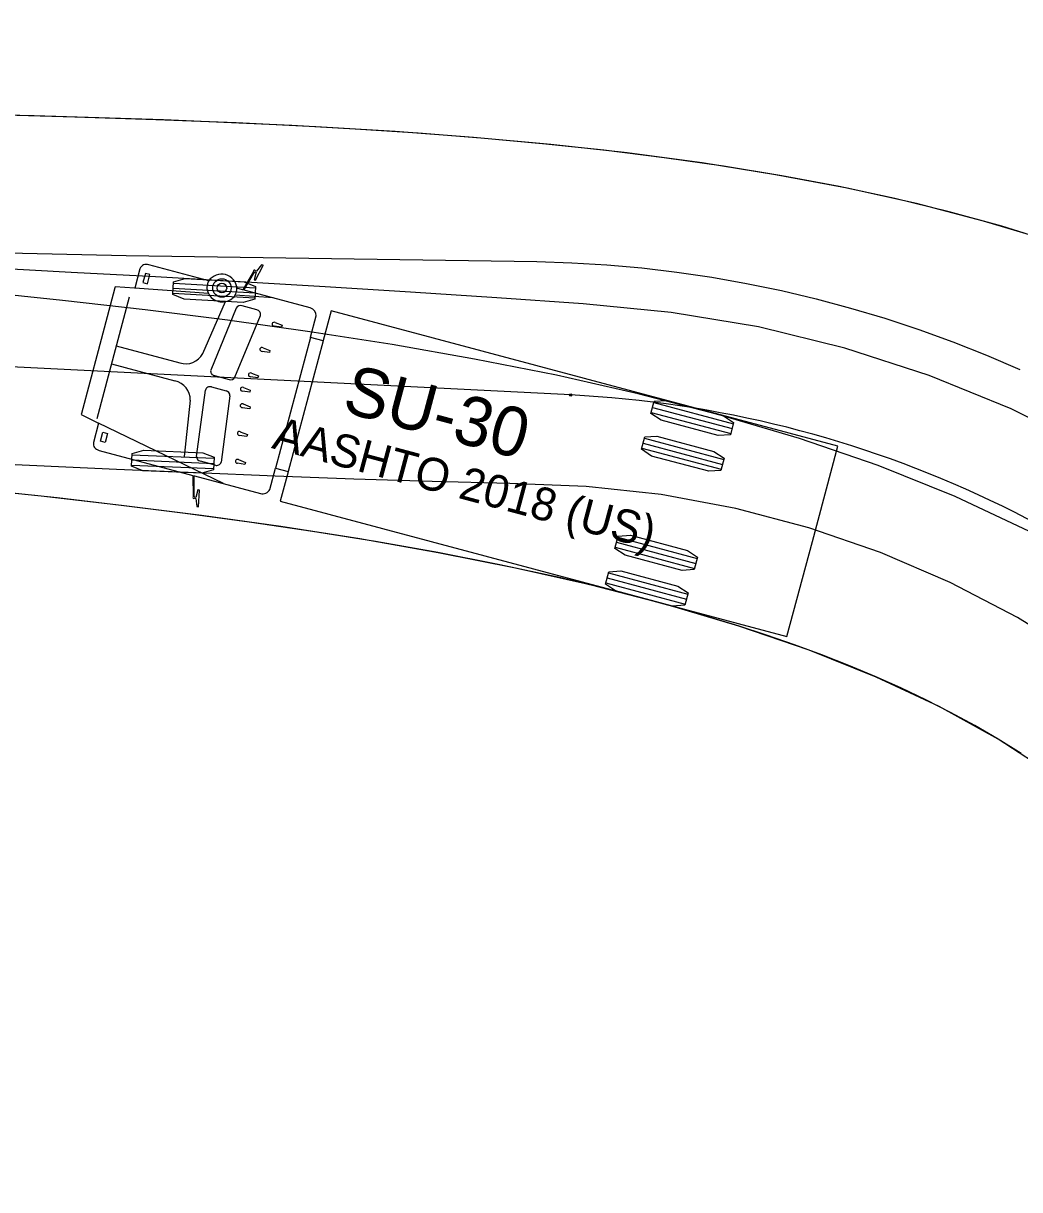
# Model space of a CAD drawing. Extents: x 260275 to 261282, y 610916 to 614143.
# Drawn here: x 261003.29 to 261043.72, y 612552.98 to 612600.34 of the extents above; entities that cross this region are included whole.
import ezdxf

# ---------------------------------------------------------------- set-up
doc = ezdxf.new("R2010")
doc.units = 0
doc.layers.add('TopoDOT_Transients', color=7, linetype='Continuous')

msp = doc.modelspace()

# ---------------------------------------------------------------- linework, layer by layer
at = {"layer": 'TopoDOT_Transients'}
for p, q in [((261025.504, 612585.252), (260776.884, 612597.696)), ((261010.818, 612589.889), (261008.381, 612590.54)), ((261008.244, 612590.188), (261008.146, 612589.822)), ((261008.432, 612590.138), (261008.244, 612590.188)), ((261008.334, 612589.772), (261008.432, 612590.138)), ((261010.801, 612589.377), (261007.813, 612589.59)), ((261008.146, 612589.822), (261008.334, 612589.772)), ((261009.371, 612589.588), (261012.699, 612589.399)), ((261009.383, 612589.796), (261012.711, 612589.607)), ((261007.587, 612589.22), (261006.269, 612584.288)), ((261009.359, 612589.38), (261012.687, 612589.191)), ((261013.429, 612589.191), (261011.884, 612589.301)), ((261010.573, 612586.933), (261011.496, 612589.042)), ((261011.933, 612588.777), (261010.898, 612586.264)), ((261012.763, 612588.712), (261012.168, 612588.871)), ((261011.876, 612585.972), (261012.912, 612588.484)), ((261013.51, 612588.196), (261013.791, 612588.084)), ((261013.769, 612588.004), (261013.471, 612588.047)), ((261013.791, 612588.084), (261013.769, 612588.004)), ((261007.061, 612587.252), (261009.639, 612586.563)), ((261013.019, 612587.171), (261013.299, 612587.059)), ((261014.943, 612587.592), (261013.525, 612582.286)), ((261015.456, 612587.454), (261014.038, 612582.149)), ((261013.278, 612586.979), (261012.979, 612587.022)), ((261013.299, 612587.059), (261013.278, 612586.979)), ((261006.864, 612586.512), (261009.441, 612585.823)), ((261011.046, 612586.037), (261011.642, 612585.878)), ((261012.813, 612585.947), (261012.514, 612585.989)), ((261012.554, 612586.139), (261012.834, 612586.026)), ((261012.834, 612586.026), (261012.813, 612585.947)), ((261010.325, 612582.76), (261010.681, 612585.454)), ((261010.923, 612585.577), (261011.519, 612585.418)), ((261012.483, 612585.364), (261012.184, 612585.407)), ((261012.224, 612585.556), (261012.504, 612585.444)), ((261012.504, 612585.444), (261012.483, 612585.364)), ((261010.066, 612585.037), (261009.815, 612582.76)), ((261011.675, 612585.22), (261011.319, 612582.526)), ((261012.219, 612584.886), (261012.5, 612584.774)), ((261028.884, 612584.948), (261032.105, 612584.087)), ((261012.478, 612584.694), (261012.179, 612584.737)), ((261012.5, 612584.774), (261012.478, 612584.694)), ((261028.777, 612584.545), (261031.997, 612583.684)), ((261028.831, 612584.746), (261032.051, 612583.886)), ((261011.415, 612581.655), (261006.349, 612584.111)), ((261006.424, 612583.378), (261006.522, 612583.744)), ((261006.611, 612583.328), (261006.424, 612583.378)), ((261006.522, 612583.744), (261006.709, 612583.694)), ((261006.709, 612583.694), (261006.611, 612583.328)), ((261012.366, 612583.568), (261012.054, 612583.613)), ((261012.094, 612583.762), (261012.387, 612583.647)), ((261012.387, 612583.647), (261012.366, 612583.568)), ((261028.497, 612583.498), (261031.717, 612582.638)), ((261028.389, 612583.096), (261031.61, 612582.235)), ((261028.443, 612583.297), (261031.664, 612582.436)), ((261007.693, 612582.614), (261011.023, 612582.472)), ((261007.702, 612582.822), (261011.032, 612582.68)), ((261011.077, 612582.402), (261010.481, 612582.562)), ((261012.281, 612582.434), (261011.982, 612582.477)), ((261012.022, 612582.626), (261012.302, 612582.514)), ((261012.302, 612582.514), (261012.281, 612582.434)), ((261007.684, 612582.406), (261011.014, 612582.263)), ((261027.367, 612579.272), (261030.588, 612578.411)), ((261027.421, 612579.473), (261030.641, 612578.612)), ((261027.314, 612579.071), (261030.534, 612578.21)), ((261026.98, 612577.823), (261030.2, 612576.962)), ((261027.034, 612578.024), (261030.254, 612577.163)), ((261026.926, 612577.621), (261030.147, 612576.761))]:
    msp.add_line(p, q, dxfattribs=at)
for points in [[(261045.064, 612591.464), (261043, 612592.102), (261040.864, 612592.69), (261038.66, 612593.227), (261036.396, 612593.714), (261034.077, 612594.152), (261031.71, 612594.542), (261029.299, 612594.888), (261026.85, 612595.192), (261024.367, 612595.457), (261021.855, 612595.686), (261019.319, 612595.883), (261016.76, 612596.051), (261014.183, 612596.194), (261008.981, 612596.419), (261003.728, 612596.585), (260998.439, 612596.713)], [(261044.857, 612591.532), (261042.252, 612592.316), (261039.535, 612593.021), (261036.72, 612593.648), (261033.818, 612594.197), (261030.84, 612594.673), (261027.798, 612595.08), (261024.702, 612595.424), (261021.559, 612595.711), (261018.378, 612595.948), (261015.165, 612596.142), (261011.927, 612596.301), (261008.666, 612596.43), (261005.384, 612596.537), (261002.085, 612596.628)], [(261002.039, 612591.033), (261007.472, 612590.914), (261024.126, 612590.67), (261025.547, 612590.623), (261026.969, 612590.536), (261028.39, 612590.409), (261029.81, 612590.241), (261031.228, 612590.031), (261032.643, 612589.781), (261034.054, 612589.49), (261035.461, 612589.156), (261036.861, 612588.782), (261038.255, 612588.366), (261039.639, 612587.908), (261041.012, 612587.408), (261042.375, 612586.868), (261043.725, 612586.285)], [(261012.691, 612590.251), (261012.734, 612590.24), (261012.735, 612590.239), (261012.661, 612589.93), (261012.66, 612589.928), (261012.714, 612589.914), (261012.716, 612589.916), (261013.02, 612590.514), (261013.021, 612590.517), (261012.958, 612590.533), (261012.755, 612590.282), (261012.754, 612590.282), (261012.708, 612590.294)], [(261046.595, 612583.097), (261043.377, 612584.693), (261040.048, 612586.05), (261036.627, 612587.159), (261033.132, 612588.013), (261029.582, 612588.608), (261026.016, 612588.949), (261022.502, 612589.202), (261019.01, 612589.433), (261015.54, 612589.648), (261012.09, 612589.851), (261008.657, 612590.044), (261005.24, 612590.231), (261001.835, 612590.413)], [(261008.023, 612590.373), (261007.814, 612589.593), (261007.808, 612589.59), (261007.025, 612589.646), (261007.012, 612589.605), (261006.329, 612587.051), (261005.647, 612584.497), (261005.638, 612584.456), (261006.345, 612584.113), (261006.348, 612584.108), (261006.139, 612583.328)], [(261012.627, 612590.274), (261012.627, 612590.273), (261012.194, 612589.528), (261012.181, 612589.524), (261011.96, 612589.583)], [(261014.936, 612588.788), (261012.256, 612589.504), (261012.246, 612589.512), (261012.669, 612590.245), (261012.669, 612590.245)], [(261044.12, 612579.713), (261041.106, 612581.131), (261037.984, 612582.383), (261034.784, 612583.484), (261031.532, 612584.452), (261028.243, 612585.302), (261024.93, 612586.051), (261021.602, 612586.712), (261018.264, 612587.298), (261014.922, 612587.821), (261011.576, 612588.289), (261008.23, 612588.711), (261004.883, 612589.094), (261001.538, 612589.444)], [(261013.292, 612581.417), (261013.524, 612582.283), (261013.528, 612582.285), (261014.037, 612582.149), (261014.035, 612582.138), (261013.714, 612580.937), (261034.279, 612575.44), (261035.312, 612579.305), (261036.345, 612583.169), (261015.78, 612588.666), (261015.459, 612587.465), (261015.455, 612587.455), (261014.946, 612587.591), (261014.944, 612587.595), (261015.175, 612588.46)], [(261006.367, 612583.004), (261010.167, 612581.989), (261010.176, 612581.979), (261010.18, 612581.118), (261010.18, 612581.117)], [(261046.246, 612574.588), (261043.631, 612576.217), (261040.904, 612577.644), (261038.079, 612578.862), (261035.173, 612579.864), (261032.201, 612580.647), (261029.181, 612581.205), (261026.128, 612581.537), (261023.039, 612581.653), (261019.885, 612581.734), (261016.711, 612581.836), (261013.518, 612581.955), (261010.307, 612582.086), (261007.08, 612582.225), (261003.838, 612582.372), (261000.584, 612582.524)], [(261010.23, 612581.121), (261010.23, 612581.121), (261010.229, 612581.967), (261010.242, 612581.969), (261012.922, 612581.252)], [(261043.789, 612570.691), (261042.855, 612571.271), (261041.9, 612571.828), (261040.923, 612572.36), (261039.923, 612572.868), (261038.901, 612573.354), (261037.855, 612573.82), (261036.787, 612574.267), (261035.697, 612574.696), (261034.584, 612575.107), (261033.452, 612575.501), (261032.302, 612575.879), (261029.954, 612576.586), (261027.553, 612577.231), (261025.107, 612577.821), (261022.626, 612578.359), (261020.115, 612578.851), (261017.579, 612579.301), (261015.023, 612579.715), (261012.451, 612580.094), (261009.864, 612580.445), (261007.267, 612580.769), (261004.659, 612581.071), (260999.422, 612581.614)], [(261058.969, 612552.742), (261057.735, 612555.289), (261056.351, 612557.734), (261054.819, 612560.07), (261053.144, 612562.287), (261051.331, 612564.376), (261049.387, 612566.327), (261047.319, 612568.133), (261045.137, 612569.785), (261042.849, 612571.275), (261040.462, 612572.599), (261037.905, 612573.799), (261035.184, 612574.889), (261032.334, 612575.869), (261029.384, 612576.746), (261026.355, 612577.528), (261023.265, 612578.226), (261020.127, 612578.849), (261016.951, 612579.406), (261013.747, 612579.907), (261010.518, 612580.359), (261007.272, 612580.769), (261004.01, 612581.142), (261000.737, 612581.485)], [(261010.24, 612581.059), (261010.285, 612581.046), (261010.286, 612581.046), (261010.337, 612580.727), (261010.4, 612580.71), (261010.4, 612580.713), (261010.435, 612581.382), (261010.435, 612581.385), (261010.381, 612581.4), (261010.38, 612581.397), (261010.29, 612581.093), (261010.289, 612581.093), (261010.247, 612581.105)]]:
    msp.add_lwpolyline(points, dxfattribs=at)
for points in [[(261009.356, 612589.329), (261009.386, 612589.848), (261009.861, 612589.978), (261012.257, 612589.842), (261012.714, 612589.659), (261012.684, 612589.14), (261012.209, 612589.01), (261009.813, 612589.146)], [(261028.763, 612584.495), (261028.898, 612584.998), (261029.389, 612585.028), (261031.708, 612584.409), (261032.118, 612584.137), (261031.984, 612583.634), (261031.492, 612583.604), (261029.174, 612584.223)], [(261028.376, 612583.046), (261028.51, 612583.548), (261029.002, 612583.579), (261031.32, 612582.96), (261031.731, 612582.688), (261031.596, 612582.185), (261031.105, 612582.154), (261028.786, 612582.774)], [(261007.682, 612582.355), (261007.704, 612582.874), (261008.177, 612583.011), (261010.575, 612582.908), (261011.034, 612582.731), (261011.012, 612582.212), (261010.539, 612582.075), (261008.141, 612582.178)], [(261027.3, 612579.021), (261027.434, 612579.523), (261027.926, 612579.554), (261030.244, 612578.934), (261030.655, 612578.662), (261030.52, 612578.16), (261030.029, 612578.129), (261027.711, 612578.749)], [(261026.913, 612577.572), (261027.047, 612578.074), (261027.538, 612578.105), (261029.857, 612577.485), (261030.267, 612577.213), (261030.133, 612576.711), (261029.642, 612576.68), (261027.323, 612577.3)]]:
    msp.add_lwpolyline(points, close=True, dxfattribs=at)
for centre, radius in [((261011.351, 612589.596), 0.374), ((261011.351, 612589.596), 0.193), ((261025.504, 612585.252), 0.0417), ((261025.504, 612585.252), 0.0417)]:
    msp.add_circle(centre, radius, dxfattribs=at)
for centre, radius, start, end in [((261039.099, 612576.697), 42, 357.1255, 114.9182), ((261008.287, 612590.275), 0.282, 70.4078, 159.4872), ((261011.334, 612589.531), 0.628, 4.7889, 145.2806), ((261012.668, 612590.283), 0.0418, 15.5288, 192.5437), ((261012.67, 612590.288), 0.0434, 268.9491, 299.6219), ((261011.268, 612589.618), 0.526, 148.9808, 207.2268), ((261011.436, 612589.573), 0.524, 307.2946, 1.0947), ((261011.361, 612589.664), 0.629, 207.0812, 255.7705), ((261011.376, 612589.661), 0.63, 254.3904, 306.7932), ((261012.105, 612588.689), 0.193, 70.9787, 152.8932), ((261012.733, 612588.53), 0.184, 345.6282, 80.4994), ((261014.853, 612588.476), 0.323, 357.1872, 75.0356), ((261013.476, 612588.137), 0.0909, 172.5195, 266.7547), ((261013.47, 612588.114), 0.091, 63.3522, 157.516), ((261012.978, 612587.089), 0.091, 63.3522, 157.516), ((261009.89, 612587.294), 0.773, 251.061, 332.1451), ((261012.984, 612587.112), 0.0909, 172.5195, 266.7547), ((261011.077, 612586.219), 0.184, 165.6337, 260.4939), ((261009.294, 612585.065), 0.773, 357.9261, 79.0102), ((261011.705, 612586.06), 0.193, 250.9738, 332.8981), ((261012.519, 612586.08), 0.0909, 172.5195, 266.7547), ((261012.513, 612586.057), 0.091, 63.3522, 157.516), ((261010.859, 612585.405), 0.184, 69.5773, 164.4375), ((261011.483, 612585.229), 0.193, 357.1731, 79.0974), ((261012.183, 612585.474), 0.091, 63.3522, 157.516), ((261012.189, 612585.497), 0.091, 172.5552, 266.7191), ((261012.179, 612584.805), 0.0909, 63.3165, 157.5517), ((261012.185, 612584.828), 0.091, 172.5552, 266.7191), ((261023.254, 612540.309), 45, 357.1255, 87.1346), ((261012.072, 612583.701), 0.091, 172.5552, 266.7191), ((261012.066, 612583.678), 0.0909, 63.3165, 157.5517), ((261006.417, 612583.282), 0.282, 170.584, 259.6634), ((261010.518, 612582.751), 0.193, 177.178, 259.0925), ((261011.141, 612582.575), 0.184, 249.5718, 344.443), ((261011.987, 612582.568), 0.091, 172.5552, 266.7191), ((261011.981, 612582.545), 0.0909, 63.3165, 157.5517), ((261010.211, 612581.088), 0.0418, 137.5275, 314.5425), ((261010.209, 612581.083), 0.0434, 30.4493, 61.1221), ((261013.005, 612581.564), 0.323, 255.0356, 332.884)]:
    msp.add_arc(centre, radius, start, end, dxfattribs=at)

# ---------------------------------------------------------------- texts
for s, height, p in [('SU-30', 2, (261016.17, 612584.587)), ('AASHTO 2018 (US)', 1.33333, (261013.333, 612583.102))]:
    msp.add_text(s, height=height, rotation=345.0356, dxfattribs=at).set_placement(p)

doc.saveas('drawing.dxf')
